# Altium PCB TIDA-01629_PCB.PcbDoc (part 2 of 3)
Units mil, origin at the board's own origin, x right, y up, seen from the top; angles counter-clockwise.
Board outline 2351.88 x 2559.06 mil, 4 copper layers (Top Layer, GND, POWER, Bottom Layer), stack 60.63 mil thick; 223 components, 122 nets, 655 pads, 542 vias.
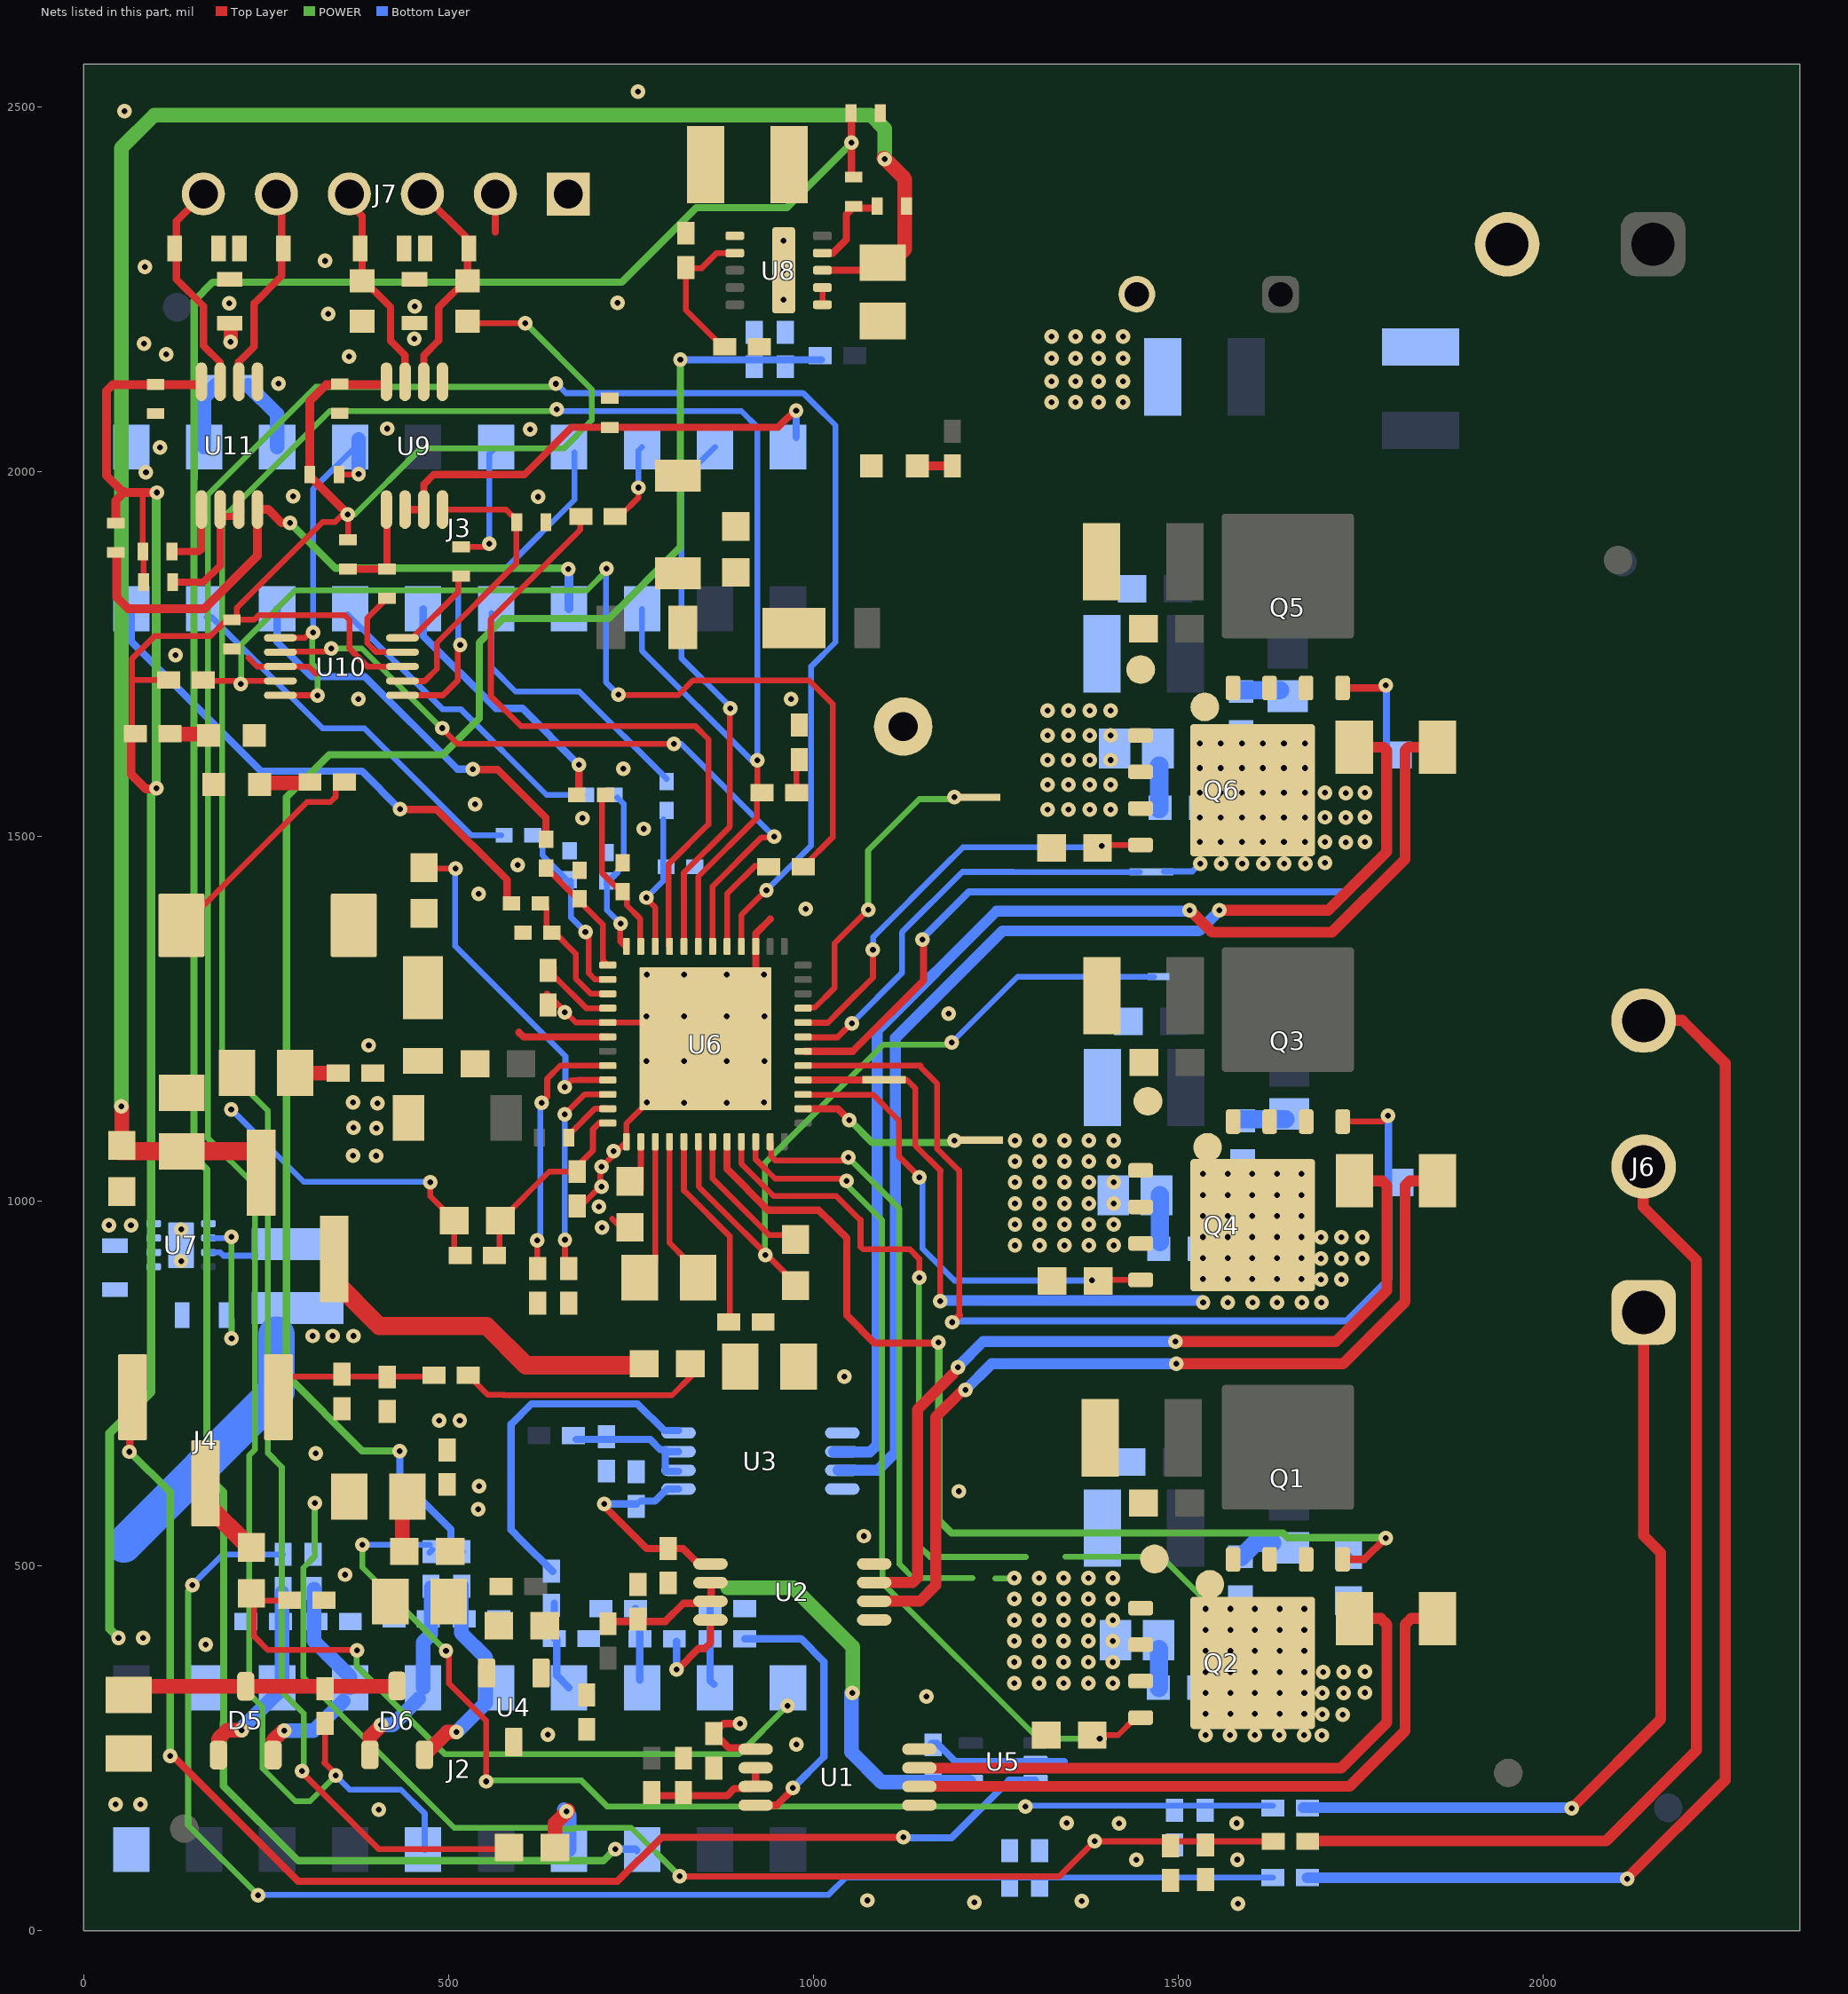
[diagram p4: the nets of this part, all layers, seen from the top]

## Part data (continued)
R5 R9 R14 R16: library part CMP-0026822-2, "RES, 0, 5%, 0.063 W, 0402", Manufacturer=Vishay-Dale, Power_W=63mW, Supplier Part Number 1=541-0.0JCT-ND, TempCo="200 ppm/C", Tolerance_%=5%, Value2=0.063W, Value_Code=0000, ValueDisplayed=0
R13: library part CMP-0022321-5, "RES, 301, 1%, 0.1 W, AEC-Q200 Grade 0, 0603", Manufacturer=Vishay-Dale, Power_W=100mW, Supplier Part Number 1=541-301HCT-ND, TempCo="100 ppm/C", Tolerance_%=1%, Value2=0.1W, Value_Code=301R, ValueDisplayed=301
R15: library part CMP-0022270-4, "RES, 2.10 k, 1%, 0.1 W, AEC-Q200 Grade 0, 0603", Manufacturer=Vishay-Dale, Power_W=100mW, Supplier Part Number 1=541-2.10KHCT-ND, TempCo="100 ppm/C", Tolerance_%=1%, Value2=0.1W, Value_Code=2k10, ValueDisplayed=2.10k
R18: library part CMP-0025958-3, "RES, 10.0 k, 1%, 0.063 W, AEC-Q200 Grade 0, 0402", Manufacturer=Vishay-Dale, Power_W=63mW, Supplier Part Number 1=541-10.0KLCT-ND, TempCo="100 ppm/C", Tolerance_%=1%, Value2=0.063W, Value_Code=10k0, ValueDisplayed=10.0k
R19: library part CMP-0026050-3, "RES, 17.4 k, 1%, 0.063 W, AEC-Q200 Grade 0, 0402", Manufacturer=Vishay-Dale, Power_W=63mW, Supplier Part Number 1=541-17.4KLCT-ND, TempCo="100 ppm/C", Tolerance_%=1%, Value2=0.063W, Value_Code=17k4, ValueDisplayed=17.4k
R20 R22 R23 R32 R33 R36: library part CMP-0020521-2, "RES, 2.7, 5%, 0.125 W, 0805", Manufacturer=Vishay-Dale, Power_W=125mW, Supplier Part Number 1=541-2.7ACT-ND, TempCo="200 ppm/C", Tolerance_%=5%, Value2=0.125W, Value_Code=2R70, ValueDisplayed=2.7
R24 R25 R26 R27 R28 R29: library part CMP-0026164-2, "RES, 20.0, 1%, 0.063 W, AEC-Q200 Grade 0, 0402", Manufacturer=Vishay-Dale, Power_W=63mW, Supplier Part Number 1=541-20.0LCT-ND, TempCo="100 ppm/C", Tolerance_%=1%, Value2=0.063W, Value_Code=20R0, ValueDisplayed=20.0
R30: library part CMP-0026852-2, "RES, 1.0 k, 5%, 0.063 W, 0402", Manufacturer=Vishay-Dale, Power_W=63mW, Supplier Part Number 1=541-1.0KJCT-ND, TempCo="200 ppm/C", Tolerance_%=5%, Value2=0.063W, Value_Code=1k00, ValueDisplayed=1.0k
R31 R46 R47 R48 R49 R51 R52 R53 R56 R57: library part CMP-0026880-3, "RES, 22, 5%, 0.063 W, AEC-Q200 Grade 0, 0402", Manufacturer=Vishay-Dale, Power_W=63mW, Supplier Part Number 1=541-22JCT-ND, TempCo="200 ppm/C", Tolerance_%=5%, Value2=0.063W, Value_Code=22R0, ValueDisplayed=22
R34: library part CMP-0026404-2, "RES, 49.9, 1%, 0.063 W, AEC-Q200 Grade 0, 0402", Manufacturer=Vishay-Dale, Power_W=63mW, Supplier Part Number 1=541-49.9LCT-ND, TempCo="100 ppm/C", Tolerance_%=1%, Value2=0.063W, Value_Code=49R9, ValueDisplayed=49.9
R35: library part CMP-0026825-4, "RES, 10 k, 5%, 0.063 W, 0402", Manufacturer=Vishay-Dale, Power_W=63mW, Supplier Part Number 1=541-10KJCT-ND, TempCo="200 ppm/C", Tolerance_%=5%, Value2=0.063W, Value_Code=10k0, ValueDisplayed=10k
R37 R45: library part CMP-0020442-2, "RES, 0, 5%, 0.125 W, 0805", Manufacturer=Vishay-Dale, Power_W=125mW, Supplier Part Number 1=541-0.0ACT-ND, TempCo="200 ppm/C", Tolerance_%=5%, Value2=0.125W, Value_Code=0000, ValueDisplayed=0
R38: library part CMP-0026162-2, "RES, 20.0 k, 1%, 0.063 W, AEC-Q200 Grade 0, 0402", Manufacturer=Vishay-Dale, Power_W=63mW, Supplier Part Number 1=541-20.0KLCT-ND, TempCo="100 ppm/C", Tolerance_%=1%, Value2=0.063W, Value_Code=20k0, ValueDisplayed=20.0k
R39: library part CMP-0026879-3, "RES, 22 k, 5%, 0.063 W, AEC-Q200 Grade 0, 0402", Manufacturer=Vishay-Dale, Power_W=63mW, Supplier Part Number 1=541-22KJCT-ND, TempCo="200 ppm/C", Tolerance_%=5%, Value2=0.063W, Value_Code=22k0, ValueDisplayed=22k
R40: library part CMP-0026646-1, "RES, 0.91, 1%, 0.125 W, 0402", Manufacturer=Panasonic, Power_W=125mW, Supplier Part Number 1=P.91AKCT-ND, TempCo="250 ppm/C", Tolerance_%=1%, Value2=0.125W, Value_Code=R910, ValueDisplayed=0.91
R41: library part CMP-0026280-2, "RES, 301 k, 1%, 0.063 W, AEC-Q200 Grade 0, 0402", Manufacturer=Vishay-Dale, Power_W=63mW, Supplier Part Number 1=541-301KLCT-ND, TempCo="100 ppm/C", Tolerance_%=1%, Value2=0.063W, Value_Code=301k
R42: library part CMP-0025956-2, "RES, 107 k, 1%, 0.063 W, 0402", Manufacturer=Vishay-Dale, Power_W=63mW, Supplier Part Number 1=541-107KLCT-ND, TempCo="100 ppm/C", Tolerance_%=1%, Value2=0.063W, Value_Code=107k
R43: library part CMP-0026405-2, "RES, 4.02 k, 1%, 0.063 W, AEC-Q200 Grade 0, 0402", Manufacturer=Vishay-Dale, Power_W=63mW, Supplier Part Number 1=541-4.02KLCT-ND, TempCo="100 ppm/C", Tolerance_%=1%, Value2=0.063W, Value_Code=4k02, ValueDisplayed=4.02k
R44: library part CMP-0026856-5, "RES, 1.5 k, 5%, 0.063 W, AEC-Q200 Grade 0, 0402", Manufacturer=Vishay-Dale, Power_W=63mW, Supplier Part Number 1=541-1.5KJCT-ND, TempCo="200 ppm/C", Tolerance_%=5%, Value2=0.063W, Value_Code=1k50, ValueDisplayed=1.5k
R50 R54: library part CMP-0025758-3, "RES, 22, 5%, 0.1 W, 0603", Manufacturer=Vishay-Dale, Power_W=100mW, Supplier Part Number 1=541-22GCT-ND, TempCo="200 ppm/C", Tolerance_%=5%, Value2=0.1W, Value_Code=22R0, ValueDisplayed=22
R55: library part CMP-0027004-2, "RES, 0, 5%, 0.063 W, 0402", Manufacturer="Yageo America", Power_W=63mW, Supplier Part Number 1=311-0.0JRCT-ND, TempCo="200 ppm/C", Tolerance_%=5%, Value2=0.063W, Value_Code=0000, ValueDisplayed=0
R58: library part CMP-0026840-2, "RES, 150 k, 5%, 0.063 W, AEC-Q200 Grade 0, 0402", Manufacturer=Vishay-Dale, Power_W=63mW, Supplier Part Number 1=541-150KJCT-ND, TempCo="200 ppm/C", Tolerance_%=5%, Value2=0.063W, Value_Code=150k
R60 R62: library part CMP-0026822-3, "RES, 0, 5%, 0.063 W, AEC-Q200 Grade 0, 0402", Manufacturer=Vishay-Dale, PartNumber=CRCW04020000Z0ED, Power_W=63mW, Supplier Part Number 1=541-0.0JCT-ND, TempCo="200 ppm/C", Tolerance_%=5%, Value2=0.063W, Value_Code=0000, ValueDisplayed=0
R61: library part CMP-0026195-2, "RES, 24.3 k, 1%, 0.063 W, AEC-Q200 Grade 0, 0402", Manufacturer=Vishay-Dale, Power_W=63mW, Supplier Part Number 1=541-24.3KLCT-ND, TempCo="100 ppm/C", Tolerance_%=1%, Value2=0.063W, Value_Code=24k3, ValueDisplayed=24.3k
R63 R65 R67 R70 R71 R73 R74 R75: library part CMP-0026938-4, "RES, 4.7 k, 5%, 0.063 W, 0402", Manufacturer=Vishay-Dale, Power_W=63mW, Supplier Part Number 1=541-4.7KJCT-ND, TempCo="200 ppm/C", Tolerance_%=5%, Value2=0.063W, Value_Code=4k70, ValueDisplayed=4.7k
R64 R72: library part CMP-0022109-5, "RES, 1.00 k, 1%, 0.1 W, AEC-Q200 Grade 0, 0603", Manufacturer=Vishay-Dale, Power_W=100mW, Supplier Part Number 1=541-1.00KHCT-ND, TempCo="100 ppm/C", Tolerance_%=1%, Value2=0.1W, Value_Code=1k00, ValueDisplayed=1.00k
R66: library part CMP-0026880-2, "RES, 22, 5%, 0.063 W, 0402", Manufacturer=Vishay-Dale, Power_W=63mW, Supplier Part Number 1=541-22JCT-ND, TempCo="200 ppm/C", Tolerance_%=5%, Value2=0.063W, Value_Code=22R0, ValueDisplayed=22
R68 R69 R76 R77: library part CMP-0023196-3, "RES, 59.0, 1%, 0.1 W, 0603", Manufacturer="Yageo America", PartNumber=RC0603FR-0759RL, Power_W=100mW, Supplier Part Number 1=311-59.0HRCT-ND, TempCo="200 ppm/C", Tolerance_%=1%, Value2=0.1W, Value_Code=59R0, ValueDisplayed=59.0
TP1: library part CMP-0055138-1, "Test Point, Miniature, Black, TH", Color=Black, Manufacturer=Keystone, Supplier Part Number 1=36-5001-ND
TP2 TP3 TP4 TP5 TP6 TP7: library part CMP-0003825-1, "1mm Test Point, SMT", Manufacturer=Any
U1 U2 U3: library part CMP-0075735-1, "High/Low Side, Bi-Directional Zero-Drift Current Sense Amp w/ Enhanced PWM Rejection, PW0008A (TSSOP-8)", Alternate Manufacturer="Texas Instruments", Alternate PartNumber=INA240A2PW
U4: library part CMP-0033032-1, "Automotive Catalog Low-Voltage Adjustable Precision Shunt Regulator, 15 mA, -40 to 125 degC, 3-pin SOT-23 (DBZ), Green (RoHS & no Sb/Br)", Manufacturer="Texas Instruments", Rating=Automotive
U5: library part CMP-0013250-2, "TMP235DCK, DCK0005A (SOT-5)", Alternate Manufacturer="Texas Instruments"
U6: library part CMP-0013783-2, "100-V Three-Phase Smart Gate Driver, RGZ0048L (VQFN-48)", Alternate Manufacturer="Texas Instruments", Alternate PartNumber=DRV8350RSRGZT
U7: library part CMP-0037789-2, "Buck Step Down Regulator with 3 to 17 V Input and 3.3 V Output, -40 to 85 degC, 8-Pin WSON (DSG), Green (RoHS & no Sb/Br)", Manufacturer="Texas Instruments", PartNumber=TPS62162DSGR, Rating=Catalog, Switch Current Limit(Typ)(A)=1.8
U8: library part CMP-0065261-5, "36-V 1-A Step-Down DC-DC Nano Module, SIL0010A (uSIP-10)", Alternate Manufacturer="Texas Instruments", Alternate PartNumber=LMZM23601SILT
U9 U11: library part CMP-0074780-2, "5-V RS-485 Transceivers With +/-16-kV IEC ESD Protection, DGK0008A (VSSOP-8)", Alternate Manufacturer="Texas Instruments", Alternate PartNumber=THVD1550DGK
U10: library part CMP-0067418-1, "DUAL 10-Ohm SPDT ANALOG SWITCH, DGS0010A (VSSOP-10)", Alternate Manufacturer="Texas Instruments", Alternate PartNumber=TS5A23157DGST
ZZ1: library part CMP-0003616-3
ZZ2 ZZ3 ZZ4: library part AssemblyNote

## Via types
v1: diameter 20, hole 8, Top Layer to Bottom Layer, tented both sides, 525 vias
v2: diameter 19.68, hole 7.87, Top Layer to Bottom Layer, 17 vias

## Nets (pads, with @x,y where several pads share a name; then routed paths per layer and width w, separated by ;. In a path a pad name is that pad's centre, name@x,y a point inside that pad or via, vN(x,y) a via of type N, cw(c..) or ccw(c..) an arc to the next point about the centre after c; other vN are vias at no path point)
3V3: C58.1 C69.1 C70.1 C72.1 D5.3 D6.3 L4.1 L5.2 R30.2 R35.2 R44.2 R45.1 R64.2 R65.2 R67.2 R73.2 R74.2 R75.2 U7.6 U9.8 U10.8 U11.8 | length 4884.4
  Top Layer w8: R44.2@66.36,1638.86 66.36,1743.53 97.91,1775.08 174.32,1775.08 195.1,1795.86 210.1,1795.86 210.1,1813.45 327.77,1931.12 344.88,1931.12 355.22,1941.46 v1(362.08,1941.46) 362.5,1941.46 R65.2@362.5,1906.81 ; 67.14,1714.81 R30.2@116.85,1714.81 ; R73.2@81.41,1890.81 81.41,1971.59 ; R75.2@82.21,1848.63 R73.2@82.21,1886.42 ; C70.1@203.34,1797.12 233.8,1797.12 239.94,1803.26 304.97,1803.26 305.08,1803.37 358.29,1803.37 364.4,1797.26 364.4,1758.84 364.91,1758.33 ; 364.23,1758.16 389.34,1733.06 U10.8@437.16,1733.06 ; R64.2@527.35,2203.62 v1(605.28,2203.62)
  Top Layer w12: R74.2@44.31,1929.59 44.31,1960.78 56.26,1972.73 ; 54.55,2119.28 40.15,2119.28 31.54,2110.66 31.54,1994.55 53.36,1972.73 56.26,1972.73 ; 54.55,2119.36 161.96,2119.36 U11.8@162.53,2119.93 ; 56.32,1972.79 56.26,1972.73 ; R44.2@65.34,1634.99 65.34,1585.57 85.47,1565.43 v1@99.57,1565.43 ; v1(100.57,1971.59) 81.41,1971.59 57.4,1971.59 56.26,1972.73 ; v1@362.63,1941.82 362.54,1941.92 310.36,1994.09 310.36,2097.06 332.67,2119.36 U9.8@415.07,2119.36
  Top Layer w20: R45.1@68.03,326.66 76.93,335.56 D6.3@418.4,335.56
  POWER w8: v1@203.08,815.86 203.08,838.23 v1(203.05,951.31) ; v1@362.54,1941.54 371.93,1941.54 462.28,2031.89 658.05,2031.89 696.49,2070.33 696.49,2112.53 ; v1@605.61,2203.9 696.74,2112.78
  POWER w12: v1@50.02,400.32 36.04,414.3 36.04,682.45 92.66,739.07 92.66,1559.22 v1(99.92,1566.48) v1@99.92,1972.3
  Bottom Layer w8: U7.6@171.25,949.74 v1@206.09,949.74
  Bottom Layer w50: 55.24,529.82 264.61,739.19 264.61,817.47
  other v1: 48.06,401.79 82.04,401.79 487.35,699.56 515.73,699.56 203.08,812.34 314.01,815.51 341.67,815.51 370.05,815.51
3V3_Analog: C1.1 C5.1 C8.1 C12.1 C56.1 L4.2 R13.1 U1.5 U2.5 U3.5 U5.4 | length 971.4
  Top Layer w10: v1@712.12,583.83 771.66,524.29 C5.1@801,524.29 ; C5.1@802.8,525.3 803.82,524.29 821.86,524.29 843.01,503.14 U2.5@859.19,503.14 ; v1(899.79,284.39) 877.5,284.39 C1.1@863.72,270.62 865.03,270.62 884.47,251.18 U1.5@925.57,251.18
  Top Layer w20: R13.1@436.7,519.49 C56.1@436.7,571.13
  POWER w20: 882.91,470.37 973.06,470.37 1054,389.43 v1@1054,326.88
  Bottom Layer w10: v1(713.58,585.41) C8.1@758.05,585.41 ; C8.1@764.23,589.41 783.08,589.41 799.53,605.87 U3.5@815.45,605.87
  Bottom Layer w20: v1@1052.26,326.3 1052.26,245.28 1093.69,203.86 U5.4@1213.39,203.86
  other v1: 1053.42,326.3 540.96,577.88 542,609.49
3V3_Launch: J2.1 R45.2
  other v1: 44.2,173.76 78.18,173.76
15V: C67.1 J1.1 L6.1 R37.2 R60.2 U8.3 | length 2896.3
  Top Layer w10: U8.3@1012.64,2276.19 C67.1@1084.73,2276.19
  Top Layer w20: L6.1@52.61,1076.67 v1@52.61,1129.8 ; v1@1097.01,2430.11 1125.62,2401.5 1125.62,2305.16 C67.1@1102.92,2282.45
  Top Layer w25: L6.1@49.3,1068.7 R37.2@134.58,1068.7 J1.1@224.43,1068.7
  POWER w20: v1(52.02,1130.38) 52.02,2444.05 96.87,2488.9 1079.17,2488.9 1097.77,2470.29 v1@1097.77,2428.98
  other v1: 1098.1,2428.53
CLK_N: J7.6 R77.2 U11.7 | length 352.1
  Top Layer w10: 127.35,2264.04 163.88,2227.51 ; 127.44,2263.94 127.44,2343.8 J7.6@164.41,2380.76 ; U11.7@187.02,2123.48 187.02,2150.38 164.93,2172.47 ; 164.93,2172.47 164.5,2172.9 164.5,2226.89 164.03,2227.36 164.93,2172.47
CLK_P: J7.5 R76.1 U11.6 | length 284.7
  Top Layer w10: U11.6@212.61,2123.48 212.61,2150.65 233.87,2171.91 233.87,2230.87 271.55,2268.55 271.55,2306.12 271.55,2373.62 J7.5@264.41,2380.76
DATA_N: J7.4 R69.2 R72.2 U9.7 | length 289.3
  Top Layer w10: J7.4@364.41,2380.76 364.41,2368.12 381.86,2350.67 381.86,2263.96 382.6,2263.96 420.66,2225.9 420.66,2179.56 440.72,2159.51 U9.7@440.72,2123.48
DATA_P: J7.3 R64.1 R68.1 U9.6 | length 285
  Top Layer w10: U9.6@466.31,2123.48 466.31,2159.51 486.68,2179.88 486.68,2225.03 525.73,2264.08 526.4,2264.08 R68.1@526.4,2306.12 ; J7.3@469.71,2376.21 R68.1@524.21,2321.72
EN_DRV: R57.2 U6.33 | length 926.1
  Top Layer w8: 579.44,1819.27 680.99,1920.81 R57.2@680.99,1937.42 ; 579.53,1819.18 558.26,1797.91 558.26,1692.61 599.25,1651.63 837.99,1651.63 856.54,1633.08 856.54,1517.27 ; U6.33@803.15,1349.48 802.03,1350.6 802.03,1462.76 856.54,1517.27 ; 856.54,1516.34 856.54,1517.27
ENC_CLK: J3.13 R74.1 U11.4 | length 868.3
  Top Layer w12: R74.1@45.45,1885.47 45.45,1828.05 61.41,1812.08 165.72,1812.08 238.51,1884.88 U11.4@238.51,1948.28 253.36,1948.28 271.78,1929.86 v1@282.18,1929.86
  POWER w10: v1(282.98,1930.05) 345.03,1868 v1@665.41,1868
  Bottom Layer w12: v1@664.96,1870.24 665.44,1869.76 J3.13@665.44,1812.21
  other v1: 664.42,1866.85
ENC_DIRCTRL: J3.20 R71.2 U9.2 U9.3 | length 652
  Top Layer w10: U9.2@440.72,1948.28 U9.3@465.85,1948.28 ; U9.3@469.18,1945.41 U9.3@466.31,1948.28 466.31,1982.51 480.01,1996.22 604.32,1996.22 669.01,2060.91 951.99,2060.91 v1@975.95,2084.87
  Bottom Layer w10: J3.20@976.65,2047.38 v1(976.65,2083.91)
ENC_PS_EN: J2.15 R62.2 R63.2 | length 3744.7
  Top Layer w10: R62.2@1052.47,2406.21 v1(1052.47,2451.19) R63.2@1052.47,2490.81
  POWER w10: v1@728.38,112.23 712.54,96.38 294.32,96.38 191.77,198.93 191.77,285.71 192.23,286.17 192.23,601.77 169.1,624.9 169.1,1043.62 151.5,1061.22 151.5,1990.24 151.76,1990.51 151.76,2234.34 177.24,2259.82 737.7,2259.82 839.77,2361.89 964.17,2361.89 v1@1053.46,2451.19
  Bottom Layer w10: v1(728.61,112.17) 756.4,112.17 J2.15@758.21,110.36
GND: C1.2 C2.2 C3.2 C4.2 C5.2 C6.2 C7.2 C8.2 C9.2 C10.2 C11.2 C12.2 C13.1 C14.2 C15.2 C16.2 C19.2 C20.2 C21.2 C22.2 C23.2 C24.2 C27.2 C29.2 C30.2 C31.2 C32.2 C34.2 C35.2 C36.2 C37.2 C38.2 C39.2 C41.2 C42.2 C43.2 C44.2 C45.2 C50.2 C51.2 C52.2 C53.2 C54.2 C55.2 C56.2 C57.2 C58.2 C59.2 C60.2 C61.2 C62.2 C63.2 C64.2 C65.2 C66.2 C67.2 C68.2 C69.2 C70.2 C71.2 C72.2 C73.2 C75.2 C77.2 C79.2 D1.2 D3.1 D4.1 D7.1 J2.4 J3.2 J5.2 J7.2 NT3.2 NT5.2 NT7.2 Q2.1 Q2.2 Q2.3 Q4.1 Q4.2 Q4.3 Q6.1 Q6.2 Q6.3 R4.1 R6.1 R10.1 R17.1 R18.1 R19.2 R22.1 R32.1 R36.1 R40.1 R42.1 R43.1 R61.1 R63.1 R70.1 R71.1 R72.1 TP1.1 TP5.1 TP6.1 TP7.1 U1.1 U1.4 U2.1 U2.4 U3.1 U3.4 U4.3 U5.2 U6.1 U6.27 U6.41 U6.49@852.36,1223.02 U7.1 U7.4 U7.5 U7.9@133.85,939.9 U8.1 U8.2 U8.11@959.49,2276.19 U9.5 U10.3 U11.5 | length 908.6
  Top Layer w7.87: 226.18,1745.01 238.14,1733.06 U10.3@269.83,1733.06 308.71,1733.06 318.34,1723.43 ; U8.1@1012.64,2228.95 U8.2@1012.64,2250.61
  Top Layer w8: C27.2@634.66,1284.4 635.56,1284.4 654.48,1265.48 674.82,1245.15 U6.41@718.5,1245.15 U6.49@790.47,1245.15 ; R43.1@680.38,992.82 708.34,1020.77 708.34,1045.65 v1@727.89,1065.19 ; 724.45,976.34 C54.2@735.06,965.73 ; v1@729.16,1066.46 v1@727.89,1065.19 ; U6.49@785.07,1147.64 744.16,1106.73 744.16,1081.83 U6.1@744.09,1081.76 727.89,1065.56 v1@727.89,1065.19
  Top Layer w10: 564.41,2328.62 J7.2@564.41,2380.76 ; U6.49@921.26,1293.16 U6.27@921.26,1349.48 921.26,1367.05 941.08,1386.88
  Top Layer w11.81: C73.2@200.26,2203.58 C73.2@201.76,2202.08
  Top Layer w19.68: v1(201.76,2177.98) C73.2@201.76,2202.08
  POWER w7.87: NT3.2@1249.47,483.07 1273.48,483.07 v1@1274.94,481.61
  Bottom Layer w9.84: C12.2@1162.1,257.48 1169.49,257.48 1194.9,232.07 U5.2@1304.56,232.07 1344,232.07
  other v1: 1582.14,37.47 1220.62,39.1 1367.83,40.9 1074.3,41.95 1442.63,97.58 1581.16,97.87 1418.92,147.34 1580.06,147.81 1347.41,148.15 404.88,166.38 976.77,255.88 636.56,269.3 1155.31,321.24 1275.6,339.75 1309.4,339.75 1343.2,339.75 1377,339.75 1410.79,339.75 1275.6,368.55 1309.4,368.55 1343.2,368.55 1377,368.55 1410.79,368.55 167.39,392.31 1275.6,397.36 1309.4,397.36 1343.2,397.36 1377,397.36 1410.79,397.36 1275.6,426.17 1309.4,426.17 1343.2,426.17 1377,426.17 1410.79,426.17 1275.6,454.97 1309.4,454.97 1343.2,454.97 1377,454.97 1410.79,454.97 1275.6,483.78 1309.4,483.78 1343.2,483.78 1377,483.78 1410.79,483.78 358.74,488.36 1069.36,541.23 1199.78,602.65 318.16,654.69 1042.49,759.75 1276.49,939.61 1310.28,939.61 1344.08,939.61 1377.88,939.61 1411.68,939.61 710.49,964.43 1276.49,968.42 1310.28,968.42 1344.08,968.42 1377.88,968.42 1411.68,968.42 706.11,992.63 1276.49,997.23 1310.28,997.23 1344.08,997.23 1377.88,997.23 1411.68,997.23 709.84,1020.34 1276.49,1026.03 1310.28,1026.03 1344.08,1026.03 1377.88,1026.03 1411.68,1026.03 709.84,1047.39 1276.49,1054.84 1310.28,1054.84 1344.08,1054.84 1377.88,1054.84 1411.68,1054.84 369.7,1062.83 400.97,1062.41 726.23,1068.88 1276.49,1083.64 1310.28,1083.64 1344.08,1083.64 1377.88,1083.64 1411.68,1083.64 370.12,1100.86 401.39,1100.44 402.66,1134.25 369.7,1135.94 772.08,1135.96 932.74,1135.96 390.99,1213.86 1185.38,1257.31 659.7,1259.07 772.08,1310.87 932.74,1310.87 989.75,1400.95 541.62,1421.43 595.22,1461.27 767.99,1510.65 683.99,1525.19 1321.21,1537.3 1350.01,1537.3 1378.82,1537.3 1407.62,1537.3 536.7,1544.54 1321.21,1571.09 1350.01,1571.09 1378.82,1571.09 1407.62,1571.09 739.97,1593.12 1321.21,1604.89 1350.01,1604.89 1378.82,1604.89 1407.62,1604.89 1321.21,1638.69 1350.01,1638.69 1378.82,1638.69 1407.62,1638.69 1321.21,1672.49 1350.01,1672.49 1378.82,1672.49 1407.62,1672.49 376.58,1688.48 969.57,1688.44 126.35,1748.61 622.89,1965.55 287.11,1966.61 85.71,1999.22 104.73,2033.08 611.98,2058.03 416.43,2059.15 1326.52,2095.16 1359.72,2095.16 1390.92,2095.16 1424.72,2095.16 267.36,2120.87 1326.52,2123.96 1359.72,2123.96 1390.92,2123.96 1424.72,2123.96 1326.52,2155.52 1359.72,2155.52 1390.92,2155.52 1424.72,2155.52 364.15,2158.18 113.61,2161 82.85,2175.46 453.45,2182.4 1326.52,2185.31 1359.72,2185.31 1390.92,2185.31 1424.72,2185.31 335.34,2216.43 453.72,2226.95 199.57,2230.91 732,2231.55 84.45,2280.88 331.27,2289.09 56.1,2494.09 760.05,2520.94
  other v2: 133.85,918.25 133.85,961.56 823.23,1134.91 881.5,1134.91 771.65,1192.12 823.23,1192.12 881.5,1192.12 933.07,1192.12 771.65,1253.93 823.23,1253.93 881.5,1253.93 933.07,1253.93 823.23,1311.13 881.5,1311.13 959.49,2235.64 959.49,2276.19 959.49,2316.74
I_A: R53.2 U1.8 | length 374.6
  Top Layer w10: U1.8@921.1,172.41 950.15,172.41 v1@972.27,194.53
  Bottom Layer w10: R53.2@906.11,400.5 983.13,400.5 1014.65,368.98 1014.65,290.91 1014.67,238.68 v1(971.92,195.93) v1@970.59,197.26
I_B: R52.2 U2.8 | length 130.4
  Top Layer w10: v1@814.2,358.35 843.02,387.17 851.54,387.17 859.19,394.82 U2.8@859.19,426.37
  Bottom Layer w10: v1(812.68,358.25) R52.2@812.68,396.96
I_C: R51.2 U3.8 | length 482.3
  Bottom Layer w10: R51.2@643.14,492.43 600.84,534.73 600.84,534.82 585.97,549.68 585.97,561.13 585.97,694.7 613.91,722.64 759.22,722.64 795.99,685.86 U3.8@815.52,685.86
MUX_CHANNEL: J3.8 R67.1 U10.1 U10.5 | length 538
  Top Layer w8: U10.5@269.83,1693.69 v1@320.99,1693.69 ; U10.1@269.83,1772.43 303.46,1772.43 311.48,1780.45 v1@316.53,1780.45 ; R67.1@350.2,1996.38 v1@377.58,1996.38
  POWER w8: v1@313.46,1775.78 313.46,1736.72 320.83,1729.36 v1@320.83,1693.41
  Bottom Layer w8: v1(314.96,1779.52) 314.96,1976.33 J3.8@371.29,2032.65
  Bottom Layer w19.68: v1(377.01,1997.08) J3.8@377.01,2044.68
  other v1: 320.54,1693.52
NetC3_1: C3.1 R5.1 U1.6 U1.7 | length 164.4
  Top Layer w10: R5.1@777.61,185.54 882.21,185.54 891.8,195.13 U1.7@914.48,195.13 ; U1.7@921.1,200.09 U1.6@921.1,223.6
NetC6_1: C6.1 R9.1 U2.6 U2.7 | length 182.2
  Top Layer w10: R9.1@712.12,424.24 797.51,424.24 822.36,449.09 856.37,449.09 860.08,452.8 U2.6@860.08,475.23
NetC9_1: C9.1 R16.1 U3.6 U3.7 | length 194.3
  Bottom Layer w10: R16.1@675.2,673.73 776.49,673.73 790.3,659.92 797.13,659.92 U3.7@797.13,657.05 ; U3.7@815.45,657.05 U3.7@797.13,657.05 ; U3.6@815.64,630.06 797.13,630.06 U3.7@797.13,657.05
NetC11_1: C11.1 R13.2 R14.2 R15.2 U4.2
NetC17_2: C17.2 NT1.1 U6.6 | length 999.1
  Top Layer w8: U6.6@842.52,1081.76 842.96,1081.32 842.96,1020.21 ; 844.36,1018.81 C17.2@966.33,896.85
  POWER w8: v1@933.94,927.59 933.94,1052.82 1095.9,1214.78 v1@1192.16,1214.78
  Bottom Layer w8: v1(1189.94,1217.87) 1279.86,1307.79 NT1.1@1467,1307.79
  other v1: 934.16,926.56
NetC18_1: C18.1 R20.1 | length 50.8
  Bottom Layer w25: C18.1@1586.34,512.29 1605.94,531.89 R20.1@1629.03,531.89
NetC23_1: C23.1 C24.1 L1.2 R21.1 U6.5 | length 607.2
  Top Layer w8: R21.1@527.46,761.47 554.25,734.68 576.15,734.68 ; 576.15,734.3 806.7,734.3 L1.2@832.6,760.2 ; U6.5@822.83,1081.76 822.83,1014.83 826.73,1010.93 ; 825.12,1012.82 885.55,952.39 C24.1@885.55,830.09
NetC25_1: C25.1 U6.4 | length 172
  Top Layer w8: U6.4@803.15,1081.76 803.15,1049.03 803.06,1048.94 803.06,943.16 C25.1@826.63,919.59
NetC25_2: C25.2 U6.3 | length 181.2
  Top Layer w8: C25.2@764.3,895.14 C25.2@764.3,895.96 ; C25.2@771.93,906.38 783.02,917.47 783.35,917.47 783.35,1043.36 783.46,1043.48 U6.3@783.46,1081.76
NetC26_2: C26.2 R22.2 | length 52.9
  Bottom Layer w25: C26.2@1474.06,333.29 R22.2@1474.06,386.22
NetC27_1: C27.1 U6.40 | length 103.8
  Top Layer w8: C27.1@644.84,1320.71 644.84,1308.83 688.84,1264.83 U6.40@718.5,1264.83
NetC28_1: C28.1 R23.1 | length 62.9
  Bottom Layer w25: C28.1@1584.08,1112.4 R23.1@1647.01,1112.4
NetC33_2: C33.2 R32.2 | length 64.5
  Bottom Layer w25: C33.2@1474.88,943.92 R32.2@1474.88,1008.42
NetC40_1: C40.1 R33.1 | length 56.9
  Bottom Layer w25: C40.1@1582.93,1700.72 R33.1@1639.85,1700.72
NetC45_1: C45.1 R34.1 | length 43.7
  Top Layer w8: R34.1@977.22,1560.13 977.22,1599.62 C45.1@980.18,1602.58
NetC46_2: C46.2 R36.2 | length 59.3
  Bottom Layer w25: C46.2@1474.12,1537.92 R36.2@1474.12,1597.17
NetC47_1: C47.1 D1.1 L2.1 U6.42 | length 124.4
  Top Layer w10: 596.76,1231.74 603.03,1225.46 U6.42@718.5,1225.46
NetC47_2: C47.2 U6.45 | length 471.9
  Top Layer w8: C47.2@463.7,1456.35 v1(509.84,1456.35) ; v1(659.44,1156.67) 669.12,1166.35 678.07,1166.35 678.12,1166.41 U6.45@718.5,1166.41
  Bottom Layer w8: v1@509.45,1456.68 509.45,1349.87 660.4,1198.92 v1@660.4,1156.59
NetC48_1: C48.1 C49.1 L2.2 R37.1 R38.2 R39.2 | length 740.7
  Top Layer w8: L2.2@135.88,1376.96 306.39,1547.47 338.55,1547.47 345.97,1554.89 345.97,1575.42 R39.2@360.46,1575.42 ; v1@475.42,1027.02 475.42,1006.67 C48.1@508.32,973.77 R38.2@508.32,932.64
  Bottom Layer w8: v1(202.51,1126.1) 301.87,1026.73 v1@475.26,1026.73
  other v1: 475.32,1026.42
NetC48_2: C48.2 R38.1 R43.2 U6.48 | length 261.5
  Top Layer w8: R38.1@570.34,929.19 C48.2@570.34,974.8 ; C48.2@571.32,973.77 638.26,1040.71 657,1040.71 ; 657,1040.8 R43.2@680.38,1040.8 ; R43.2@680.38,1040.06 R43.2@680.38,1040.8 ; U6.48@707.24,1108.04 698.18,1098.98 698.18,1069.86 680.38,1052.07 R43.2@680.38,1040.8
NetC49_2: C49.2 R40.2 | length 57.3
  Top Layer w20: C49.2@290.31,1176.07 R40.2@347.61,1176.07
NetC52_1: C52.1 C53.1 D2.1 L3.1
NetC54_1: C54.1 U6.2 | length 65.7
  Top Layer w8: C54.1@763.78,1016.03 U6.2@763.78,1081.76
NetC55_1: C55.1 U6.44 | length 365.8
  Top Layer w8: C55.1@617.09,900.94 622.03,905.88 v1(622.03,946.76) ; v1(627.77,1135.18) 635.5,1142.91 635.5,1168.15 653.44,1186.09 U6.44@718.5,1186.09
  Bottom Layer w8: v1@626.21,944.54 626.21,1133.62 v1(627.77,1135.18)
NetC57_1: C57.1 L6.2 U7.2 U7.3
  other v1: 35.11,967.51 65.11,967.48
NetC59_1: C59.1 J2.18 R53.1 | length 105.7
  Bottom Layer w10: C59.1@858.84,441.81 858.84,343.21 J2.18@863.86,338.19
NetC60_1: C60.1 J2.16 R52.1 | length 100.5
  Bottom Layer w10: C60.1@756.34,441.81 762.37,435.79 J2.16@762.37,343.77
NetC61_1: C61.1 J2.14 R51.1 | length 122.7
  Bottom Layer w10: C61.1@645.15,400.81 R51.1@645.15,449.45 ; C61.1@648.61,400.4 648.61,350.1 J2.14@665.44,333.27
NetC62_1: C62.1 J2.20 R54.2 | length 937.7
  Top Layer w8: R54.2@231.59,463.41 242.12,452.89 C62.1@284.21,452.89 ; 233.86,416.53 R54.2@233.86,449.57 ; 234.01,416.53 234.01,403.68 252.52,385.17 v1@372.43,385.17
  POWER w8: v1@374.08,383.74 374.08,363.49 495.48,242.1 898.09,242.1 v1(964.69,308.7)
  other v1: 375,384.85
NetC63_1: C63.1 D6.2 J2.12 R49.1 | length 284.4
  Top Layer w20: D6.2@467.3,241.45 498.62,272.77 v1@507.4,272.77
  Bottom Layer w20: v1(511.15,272.55) 551.61,313 551.61,374.49 517.62,408.48 R49.1@517.62,473.06
NetC64_1: C64.1 D6.1 J2.10 R48.1 | length 254.4
  Top Layer w20: D6.1@392.5,241.45 392.5,266.4 v1@407.47,281.37
  Bottom Layer w20: v1(407.87,282.59) 423.74,282.59 J2.10@459.57,318.41 ; J2.10@465.44,333.27 465.44,395.81 476.2,406.57 R48.1@476.2,470.58
NetC65_1: C65.1 D5.2 J2.8 R47.1 | length 292.3
  Top Layer w20: D5.2@259.79,241.06 259.79,260.88 v1@272.63,273.72
  Bottom Layer w20: v1(274.95,274.46) 315.39,274.46 J2.8@356.11,315.18 ; R47.1@315.88,468.88 315.88,397.45 334.21,379.11 ; 334.44,379.33 365.44,348.33 J2.8@365.44,333.27
NetC66_1: C66.1 D5.1 J2.6 R46.1 | length 272.6
  Top Layer w20: D5.1@184.99,241.06 184.99,263.27 196.84,275.12 v1@217.08,275.12
  Bottom Layer w20: v1(216.61,275.42) 216.61,276.99 J2.6@265.22,325.6 ; J2.6@265.44,333.27 272.39,340.21 272.39,392.7 ; 272.29,382.82 R46.1@272.29,463.58
NetC71_1: C71.1 R68.2 R69.1
NetC73_1: C73.1 R76.2 R77.1
NetC74_1: C74.1 Q1.4 U6.8 | length 1499.3
  Top Layer w10: U6.8@881.89,1081.76 881.89,1044.6 938.62,987.87 1007.74,987.87 1023.22,972.39 ; 1020.9,974.82 1046.02,949.7 1046.02,843.83 1083.91,805.94 v1@1172.94,805.94 ; Q1.4@1721.02,509.4 Q1.4@1721.02,514.89 ; Q1.4@1725.49,509.4 1755.37,509.4 v1(1784.69,538.72)
  POWER w10: v1@1172.24,807.34 1172.24,562.75 1189.54,545.45 1643.95,545.45 1650.4,539 v1@1781.61,539
  Bottom Layer w8: C74.1@1733.44,515.95 1740.17,509.22 1755.19,509.22 v1(1784.69,538.72)
  other v1: 1171.36,806.54
NetC75_1: C75.1 Q2.4 U6.10 | length 1208.5
  Top Layer w8: U6.10@921.26,1081.76 921.26,1057.58 947.7,1031.14 v1@1042.89,1031.14 ; C75.1@1382.24,268.5 1417.81,268.5 Q2.4@1441.36,292.05 ; Q2.4@1448.96,292.05 Q2.4@1441.36,292.05 ; Q2.4@1458.27,292.48 Q2.4@1448.68,292.48 1441.79,292.48 Q2.4@1441.36,292.05
  POWER w8: v1@1045.31,1028.89 1045.31,1023.14 1094.6,973.85 1094.6,499.12 ; 1094.79,499.12 1094.79,477.19 1307.16,264.82 1307.4,264.82 1308.49,263.74 v1@1392.45,263.74
  other v1: 1392.66,263.7 1045.91,1027.91
NetC76_1: C76.1 Q3.4 U6.17 | length 1455.8
  Top Layer w8: U6.17@980.01,1186.09 1147.28,1186.09 ; 1145.71,1185.49 1169.77,1161.43 1169.77,1093.95 1169.74,1072.07 1199.43,1042.38 1200.42,1042.38 1200.42,844.18 ; Q3.4@1725.49,1109.37 1779.7,1109.37 v1@1787.2,1116.88
  Top Layer w10: v1(1190.58,834.34) 1200.42,844.18
  Bottom Layer w10: v1@1189.68,836.27 1731.16,836.27 1788.31,893.42 v1@1788.31,1116.34
  other v1: 1787.76,1117.43
NetC77_1: C77.1 Q4.4 U6.15 | length 650
  Top Layer w8: U6.15@989.3,1145.94 1082.42,1145.94 1117.55,1110.8 1117.55,1075.51 ; 1117.58,1075.17 1117.58,1061.1 v1(1145.56,1033.13) ; C77.1@1380.69,892.41 Q4.4@1448.68,892.41
  Bottom Layer w8: v1@1144.29,1031.84 1149.9,1026.22 1149.9,935.1 1193.49,891.51 v1@1383.1,891.51
  other v1: 1382.18,891.61
NetC78_1: C78.1 Q5.4 U6.18 | length 1229.8
  Top Layer w10: U6.18@989.13,1205.66 1054.08,1205.66 1151.23,1302.8 v1@1151.23,1357.79 ; Q5.4@1725.36,1703.67 1781.29,1703.67 v1@1785.24,1707.61
  Bottom Layer w10: v1@1148.86,1359.65 1213.48,1424.27 1536.56,1424.27 1536.71,1424.12 1728.35,1424.12 1785.53,1481.31 v1@1785.53,1705.07
  other v1: 1149.82,1358.95 1784.69,1707.42
NetC79_1: C79.1 Q6.4 U6.20 | length 596.9
  Top Layer w8: U6.20@988.81,1244.83 1020.06,1244.83 1028.91,1253.69 1028.91,1253.91 1042.87,1267.88 1043.1,1267.88 1081.84,1306.62 v1(1081.84,1344.75) ; C79.1@1396.56,1488.58 Q6.4@1448.55,1488.58
  Bottom Layer w8: v1@1082.15,1344.23 1082.15,1362.39 1181.72,1461.96 ; 1177.4,1457.67 1204.93,1485.2 v1@1395.06,1485.2
  other v1: 1395.47,1487.17
NetD3_2: D3.2 R39.1 | length 58.1
  Top Layer w20: D3.2@247.04,1573.58 R39.1@305.09,1573.58
NetD4_2: D4.2 R44.1 | length 60.4
  Top Layer w20: R44.1@115.27,1640.4 D4.2@175.66,1640.4
NetD7_2: D7.2 R58.1 | length 42.4
  Top Layer w12: D7.2@1142.77,2007.97 R58.1@1185.18,2007.97
NetJ1_2: J1.2 L1.1 | length 500.2
  Top Layer w25: J1.2@343.9,918.78 343.9,890.9 405.44,829.36 552.38,829.36 606.38,775.36 L1.1@768.39,775.36
NetJ2_13: J2.13 R50.2 | length 117.6
  Top Layer w20: R50.2@646.27,111.99 646.27,147.27 v1@663.95,164.94
  Bottom Layer w20: v1@658.6,166.13 665.44,159.29 J2.13@665.44,111.62
  other v1: 661.87,163.76
NetJ3_4: J3.4 R55.2 | length 91.8
  Bottom Layer w20: J3.4@165.44,2033.86 165.44,2102.5 R55.2@181.83,2118.89
NetJ3_6: J3.6 R55.1 | length 100.8
  Bottom Layer w20: R55.1@226,2118.32 265.44,2078.88 J3.6@265.44,2033.86
NetJ3_12: J3.12 R56.1 | length 173.1
  Top Layer w8: R56.1@517.55,1896.92 v1@557.76,1896.92
  Bottom Layer w8: v1@553.64,1900.88 556.24,1903.48 556.24,2024.66 J3.12@561.92,2030.33
  other v1: 556.24,1901.46
NetJ3_16: J3.16 R57.1 | length 106.5
  Top Layer w8: R57.1@735.66,1939.68 760.7,1964.73 v1(760.7,1978.31)
  Bottom Layer w8: v1(760.7,1978.31) 760.7,2029.12 J3.16@765.44,2033.86
NetJ4_2: J4.2 R54.1 | length 104.7
  Top Layer w25: J4.2@166.98,603.83 166.98,586.71 R54.1@228.88,524.81
NetL5_1: L5.1 U7.7 | length 65.8
  Bottom Layer w8: U7.7@171.25,930.06 187.46,930.06 191.92,925.59 L5.1@235.18,925.59
NetNT2_1: NT2.1 U6.9 | length 904.3
  Top Layer w8: U6.9@901.58,1081.76 901.58,1051.57 945.92,1007.22 1031.7,1007.22 1041.26,997.66 ; 1041.18,997.53 1063.9,974.81 1064.87,974.81 1064.87,937.78 1068.32,934.33 1132.31,934.33 1145.26,921.38 v1(1145.26,895.5) v1@1143.46,895.5
  POWER w8: 1144.91,740.1 v1@1144.91,894.95 ; 1144.9,747.22 1144.9,528.08 1160.28,512.7 NT2.1@1291.6,512.7
NetNT4_1: NT4.1 U6.16 | length 101.3
  Top Layer w10: U6.16@986.22,1166.41 NT4.1@1087.51,1166.41
NetNT6_1: NT6.1 U6.19 | length 590.5
  Top Layer w8: U6.19@994.45,1224.75 1033.2,1224.75 v1@1053.83,1245.38
  Bottom Layer w8: v1(1052.75,1244.03) 1121.55,1312.83 1121.55,1368.76 1204.38,1451.59 1273.81,1451.59 ; 1264.73,1451.52 NT6.1@1447.54,1451.52
NetR15_1: R15.1 R18.2 U4.1
NetR31_2: R31.2 U6.29 | length 139
  Top Layer w8: U6.29@881.89,1349.48 881.89,1421.52 920.08,1459.7 R31.2@933.07,1459.7
NetR41_1: R41.1 U6.47 | length 70.3
  Top Layer w8: R41.1@668.59,1087.41 668.59,1094.62 701.33,1127.36 U6.47@710.09,1127.36 ; U6.47@710.09,1127.45 U6.47@718.09,1127.45
NetR42_2: R42.2 U6.46 | length 289.5
  Top Layer w8: v1(659.33,1119.34) 686.72,1146.72 U6.46@718.5,1146.72 ; v1(659.85,947.44) 659.85,905.21 R42.2@663.59,901.46
  Bottom Layer w8: v1@659.69,946.59 v1@659.69,1118
NetR59_2: R59.2 R61.2 U8.7 | length 200.3
  Top Layer w8: R59.2@825.53,2279.76 825.53,2221.54 R61.2@875.48,2171.58 ; R59.2@829.67,2279.25 847.27,2279.25 867.83,2299.81 U8.7@892.56,2299.81
NetR60_1: R60.1 R62.1 U8.4 | length 120.3
  Top Layer w10: U8.4@1012.64,2299.81 1026.98,2299.81 1045.37,2318.2 1045.37,2352.94 R62.1@1055.21,2362.78 ; R62.1@1057.28,2361.3 R60.1@1088.6,2361.3
NetR65_1: R65.1 R66.2 U9.1 | length 132.7
  Top Layer w10: R65.1@362.5,1866.81 R66.2@416.07,1866.81 ; R66.2@416.07,1866.5 R66.2@416.07,1866.81 ; U9.1@416.07,1945.63 R66.2@416.07,1866.81
NetR66_1: R66.1 U10.9 | length 124.4
  Top Layer w8: R66.1@416.07,1826.5 388.91,1799.34 388.91,1765.13 401.27,1752.76 U10.9@435.58,1752.76
NetR70_2: R70.2 U9.4 U10.7 | length 401.2
  Top Layer w8: U10.7@446.79,1713.18 467.59,1713.18 484.34,1729.92 484.34,1765.73 593.49,1874.89 593.49,1933.8 579.02,1948.28 U9.4@491.9,1948.28
NetR73_1: R73.1 U11.1 | length 96.5
  Top Layer w10: R73.1@121.41,1890.81 158.07,1890.81 161.68,1894.42 ; 161.74,1893.51 U11.1@161.74,1948.28
NetR75_1: R75.1 U11.2 U11.3 | length 165.9
  Top Layer w10: R75.1@122.21,1848.63 164.42,1848.63 187.73,1871.93 187.73,1938.68 U11.3@207.65,1938.68 ; U11.3@212.92,1948.28 U11.3@215.8,1945.41
nFault: J2.9 R35.1 U6.28 | length 3924.5
  Top Layer w8: 330.25,230.74 v1@349.03,211.97 ; 330.88,229.29 R35.1@330.88,284.77 ; U6.28@901.58,1349.48 901.58,1392.59 v1@936.59,1427.6
  POWER w8: v1(345.69,212.98) 310.48,177.77 290.49,177.77 245.29,222.98 245.29,306.87 226.92,325.23 226.92,651.66 235.01,659.74 235.01,1021.96 170.34,1086.62 170.34,1968.23 318.47,2116.36 385.86,2116.36 ; 370.89,2116.32 642.94,2116.32 v1(647.24,2120.63)
  Bottom Layer w8: v1@345.26,213.42 v1(345.69,212.98) 364.91,193.77 435.01,193.77 467.64,161.14 J2.9@467.64,111.08 ; v1@647.07,2122.18 661.46,2107.8 984.37,2107.8 984.42,2107.75 986.53,2107.75 1000.49,2093.78 1000.49,2093.68 1030.4,2063.77 1030.4,1766.36 997.23,1733.2 997.23,1487.81 v1(935.93,1426.5)
PH_A_N: C18.2 C26.1 C74.2 NT2.2 Q1.1 Q1.2 Q1.3 Q2.5 Q2.6 Q2.7 Q2.8 Q2.9@1602.22,367.48 R2.1 TP2.1 U1.3 | length 1069.2
  Top Layer w15: U1.3@1153.25,223.28 1723.4,223.28 1786.08,285.97 1786.08,420.12 1777.86,428.33 R2.1@1741.49,428.33
  POWER w8: NT2.2@1345.39,512.9 1477.12,512.9 1537.81,452.21 v1(1537.81,441.48)
  other v1: 1537.49,268.42 1571.29,268.42 1605.09,268.42 1638.89,268.42 1672.68,268.42 1697.1,268.16 1725.62,296.39 1537.81,297.45 1571.61,297.45 1605.41,297.45 1639.21,297.45 1673,297.45 1697.41,297.19 1537.81,326.26 1571.61,326.26 1605.41,326.26 1639.21,326.26 1673,326.26 1697.41,326.26 1726.9,326.26 1756.07,326.57 1537.81,355.06 1571.61,355.06 1605.41,355.06 1639.21,355.06 1673,355.06 1698.7,355.06 1726.9,355.06 1756.07,355.37 1537.81,383.87 1571.61,383.87 1605.41,383.87 1639.21,383.87 1673,383.87 1537.81,412.67 1571.61,412.67 1605.41,412.67 1639.21,412.67 1673,412.67 1571.61,441.48 1605.41,441.48 1639.21,441.48 1673,441.48
PH_A_P: J6.1 R2.2 R3.1 U1.2 | length 1990.5
  Top Layer w15: U1.2@1153.25,198.28 1735.12,198.28 1749.76,212.93 1749.76,213.07 1811.08,274.39 1811.08,420.12 1819.29,428.33 R2.2@1855.67,428.33 ; v1@2039.98,168.78 2161.41,290.21 2161.41,518.4 2137.89,541.92 J6.1@2137.89,847.77
  Bottom Layer w15: R3.1@1671.27,168.97 v1@2039.59,168.97
  other v1: 2039.16,168.25
PH_B_N: C28.2 C33.1 C76.2 NT4.2 Q3.1 Q3.2 Q3.3 Q4.5 Q4.6 Q4.7 Q4.8 Q4.9@1602.22,967.41 R7.1 TP3.1 U2.3 | length 1880.6
  Top Layer w8: NT4.2@1112.09,1166.68 1128.32,1166.68 1140.03,1154.97 1140.03,1076.55 1174.8,1041.78 ; v1@1171.06,860.8 1174.26,864.01 1174.26,1041.79
  Top Layer w15: U2.3@1083.6,477.55 1136.26,477.55 1142.81,484.1 1142.81,714.63 1191.5,763.32 ; v1(1496.58,807.93) 1716.14,807.93 1786.08,877.87 1786.08,1021.73 1779.66,1028.15 R7.1@1741.49,1028.15
  Bottom Layer w15: v1@1177.37,864.23 v1@1532,864.23 ; v1@1198.43,773.63 1232.74,807.93 v1(1496.58,807.93)
  other v1: 1198.2,772.89 1534.35,861.18 1568.14,861.18 1601.94,861.18 1635.74,861.18 1669.54,861.18 1696.16,861.18 1173.86,863.14 1695.92,893.07 1723.93,893.07 1534.11,893.55 1567.91,893.55 1601.7,893.55 1635.5,893.55 1669.3,893.55 1695.92,921.88 1723.93,921.88 1752.51,921.88 1534.11,922.35 1567.91,922.35 1601.7,922.35 1635.5,922.35 1669.3,922.35 1695.92,950.69 1723.93,950.69 1752.51,950.69 1534.11,951.16 1567.91,951.16 1601.7,951.16 1635.5,951.16 1669.3,951.16 1534.11,979.96 1567.91,979.96 1601.7,979.96 1635.5,979.96 1669.3,979.96 1534.11,1008.77 1567.91,1008.77 1601.7,1008.77 1635.5,1008.77 1669.3,1008.77 1534.11,1037.57 1567.91,1037.57 1601.7,1037.57 1635.5,1037.57 1669.3,1037.57
PH_B_P: J6.2 R7.2 R8.1 U2.2 | length 2637.5
  Top Layer w15: U2.2@1083.6,451.96 1146.03,451.96 1167.81,473.75 1167.81,704.28 v1@1206.96,743.43 ; v1(1497.55,777.41) 1725.96,777.41 1811.08,862.52 1811.08,1021.73 1817.5,1028.15 R7.2@1855.67,1028.15 ; R8.1@1684.43,123.42 2086.37,123.42 2210.36,247.41 2210.36,919.41 2137.34,992.43 J6.2@2137.34,1036.96
  POWER w15: v1@1206.99,743.4 v1(1208.7,741.69)
  Bottom Layer w15: v1(1208.7,741.69) 1244.42,777.41 v1(1497.55,777.41)
PH_C_N: C40.2 C46.1 C78.2 NT6.2 Q5.1 Q5.2 Q5.3 Q6.5 Q6.6 Q6.7 Q6.8 Q6.9@1602.1,1563.58 R11.1 TP4.1 U3.3 | length 1708.7
  Top Layer w15: v1(1556.58,1399.06) 1705.66,1399.06 1785.95,1479.35 1785.95,1618.07 1781.44,1622.58 R11.1@1741.36,1622.58
  Bottom Layer w8: NT6.2@1480.41,1452.23 1519.53,1452.23 v1(1530.26,1462.96)
  Bottom Layer w15: U3.3@1034.12,631.67 1066.97,631.67 1067.23,631.41 1087.94,631.41 1095.27,638.74 1112.79,656.26 1112.79,1224.06 1259.4,1370.66 1528.73,1370.66 v1@1558.17,1400.1 ; U3.3@1039.86,631.46 1070.98,631.46 1071.2,631.67
  other v1: 1559.07,1462.96 1587.87,1462.96 1616.68,1462.96 1645.48,1462.96 1674.29,1462.96 1701.15,1464.04 1529.81,1492.54 1558.61,1492.54 1587.42,1492.54 1616.22,1492.54 1645.03,1492.54 1673.83,1492.54 1701.15,1492.47 1729.82,1492.13 1755.95,1492.68 1729.82,1525.93 1529.81,1526.34 1558.61,1526.34 1587.42,1526.34 1616.22,1526.34 1645.03,1526.34 1673.83,1526.34 1701.15,1526.45 1755.95,1526.48 1701.15,1560.06 1729.82,1559.73 1529.81,1560.13 1558.61,1560.13 1587.42,1560.13 1616.22,1560.13 1645.03,1560.13 1673.83,1560.13 1755.95,1560.28 1529.81,1593.93 1558.61,1593.93 1587.42,1593.93 1616.22,1593.93 1645.03,1593.93 1673.83,1593.93 1529.81,1627.73 1558.61,1627.73 1587.42,1627.73 1616.22,1627.73 1645.03,1627.73 1673.83,1627.73
PH_C_P: J6.3 R11.2 R12.1 U3.2 | length 3430.7
  Top Layer w15: v1@1515.05,1400.48 1546.66,1368.87 1710.82,1368.87 1810.95,1469 1810.95,1618.07 1815.47,1622.58 R11.2@1855.54,1622.58 ; v1@2116.04,73.22 2249.91,207.1 2249.91,1189.14 2190.84,1248.21 J6.3@2127.28,1248.21
  Bottom Layer w15: U3.2@1027.66,656.67 1077.33,656.67 1077.59,656.41 1087.79,666.62 1087.79,1234.41 1251.21,1397.83 v1@1516.28,1397.83 ; R12.1@1676.75,73.05 v1@2114.52,73.05
  other v1: 2115.28,71.7 1515.76,1399.06
PWM_AH: J3.11 R24.1 | length 377.9
  Bottom Layer w8: J3.11@559.18,1806.54 559.18,1731.82 592.07,1698.93 679.35,1698.93 R24.1@799.1,1579.17
PWM_AL: J3.9 R25.1 | length 367.6
  Top Layer w10: R25.1@672.25,1557.14 678.88,1563.77 v1(678.88,1598.29)
  Bottom Layer w10: J3.9@465.44,1812.21 465.44,1775.3 564.98,1675.76 601.41,1675.76 v1(678.88,1598.29)
PWM_BH: J3.7 R26.1 | length 424.7
  Bottom Layer w8: J3.7@361.95,1804.74 492.01,1674.68 516.98,1674.68 634.52,1557.14 R26.1@684.06,1557.14
PWM_BL: J3.5 R27.1 | length 546
  Top Layer w10: v1@533.31,1591.68 568.1,1591.68 633.75,1526.03 R27.1@633.75,1493.73
  Bottom Layer w10: J3.5@265.44,1812.21 265.44,1766.71 312.79,1719.36 385.51,1719.36 512.46,1592.41 v1(533.81,1592.41)
PWM_CH: J3.3 R28.1 | length 527.9
  Bottom Layer w8: J3.3@168.67,1801.15 174.98,1801.15 327.72,1648.41 385.12,1648.41 531.63,1501.9 R28.1@572.58,1501.9
PWM_CL: J3.1 R29.1 | length 724.2
  Top Layer w10: v1@436,1537.02 484.3,1537.02 580.52,1440.8 R29.1@580.52,1409.33
  Bottom Layer w10: J3.1@65.44,1812.21 65.44,1767.47 243.38,1589.53 381.78,1589.53 v1(433.83,1537.48)
PWM_DRV_AH: C39.1 R24.2 U6.34 | length 185.9
  Top Layer w8: v1@771.88,1418.36 771.88,1414.66 783.63,1402.91 U6.34@783.63,1350.56
  Bottom Layer w8: v1(771.35,1416.35) 794.87,1439.87 C39.1@794.87,1454.65 ; C39.1@794.55,1458.58 794.55,1523.72
PWM_DRV_AL: C36.1 R25.2 U6.35 | length 224.6
  Top Layer w8: R25.2@710.4,1551.93 710.4,1450.48 744.61,1416.27 744.61,1405.7 762.66,1387.64 762.66,1350.6 U6.35@763.78,1349.48
PWM_DRV_BH: C38.1 R26.2 U6.36 | length 257.2
  Top Layer w8: v1@735.59,1381.17 735.59,1355.89 U6.36@743.02,1348.45 ; U6.36@744.09,1349.48 U6.36@744.09,1355.5
  Bottom Layer w8: C38.1@716.64,1434.99 C38.1@717.22,1435.57 ; C38.1@716.64,1438.93 718.5,1438.93 731.92,1452.36 ; R26.2@731.56,1553.48 740.32,1544.72 740.32,1460.75 731.92,1452.36 ; v1(735.92,1380.67) 717.22,1399.37 C38.1@717.22,1435.57 ; C38.1@717.22,1435.57 731.92,1450.28 731.92,1452.36
PWM_DRV_BL: C35.1 R27.2 U6.37 | length 162.1
  Top Layer w8: R27.2@638.44,1452.87 711.68,1379.63 711.68,1330.71 U6.37@718.5,1323.89
PWM_DRV_CH: C37.1 R28.2 U6.38 | length 247.4
  Top Layer w8: v1@687.51,1367.95 692.58,1362.88 692.58,1312.56 700.94,1304.2 U6.38@718.5,1304.2
  Bottom Layer w8: 629,1503.38 629,1474.24 C37.1@666.21,1437.02 ; C37.1@667.82,1439.94 667.82,1389.45 v1(687.84,1369.44)
PWM_DRV_CL: C34.1 R29.2 U6.39 | length 187.3
  Top Layer w8: R29.2@628.44,1410.04 634.44,1404.03 634.44,1366.92 646.94,1366.92 674.74,1339.13 674.74,1305.17 695.39,1284.52 U6.39@718.5,1284.52 ; C34.1@641.8,1368.42 C34.1@645.44,1368.42
SLA: NT3.1 U6.11 | length 822.7
  Top Layer w8: U6.11@940.95,1081.76 942.06,1080.64 942.06,1062.01 947.96,1056.11 v1@1048.97,1056.11
  POWER w8: v1@1049.24,1058.94 1118.29,989.89 1118.29,502.52 1137.03,483.78 NT3.1@1218.64,483.78
  other v1: 1047.99,1060.47
SLB: NT5.1 U6.14 | length 222.4
  Top Layer w10: U6.14@992.09,1126.92 1033.57,1126.92 v1@1051.26,1109.22
  POWER w10: v1@1051.15,1110.4 1080.93,1080.62 v1@1194.67,1080.62
  other v1: 1193.58,1083.24 1049.5,1111.2
SLC: NT7.1 U6.21 | length 409
  Top Layer w8: U6.21@986.22,1264.83 987.34,1265.95 1002.6,1265.95 1029.09,1292.44 1029.09,1353.34 v1@1074.91,1399.16
  POWER w8: v1@1075.15,1398.37 1075.15,1481.18 1145.32,1551.35 v1@1192.29,1551.35
  other v1: 1075.47,1399.53 1193.44,1553.98
SPI_CLK: J3.15 R34.2 R50.1 U6.31 | length 3924.4
  Top Layer w8: v1@297.44,219.5 404.96,111.99 R50.1@583.28,111.99 ; U6.31@842.52,1349.48 842.52,1445.14 923.07,1525.69 R34.2@923.07,1560.85 ; v1@923.53,1604.74 923.53,1566.57 R34.2@929.97,1560.13
  POWER w8: v1@301.79,217.76 301.79,298.17 271.8,328.16 271.8,635.92 252.85,654.87 252.85,1124.04 213.83,1163.05 190.23,1186.68 190.23,1936 337.43,2083.2 641.34,2083.2 v1@645.87,2087.72
  Bottom Layer w8: v1@650.39,2083.17 901.58,2083.17 923.62,2061.12 v1(923.62,1604.74) ; J3.15@765.44,1812.21 765.44,1754.63 915.77,1604.3 v1@925.88,1604.3
  other v1: 299.36,219.23 648.6,2085.42
SPI_CS: J3.18 U6.32 | length 757.7
  Top Layer w8: U6.32@822.83,1349.48 822.83,1450.69 885.93,1513.78 v1@885.93,1674.18
  Bottom Layer w8: J3.18@865.44,2033.86 819.21,1987.63 819.21,1744.75 887.47,1676.49 v1@887.47,1674.47
  other v1: 886.61,1675.63
SPI_DRV_SDI: U6.30 U10.2 | length 980.9
  Top Layer w8: U10.2@271.14,1753.37 v1@341.01,1753.37 ; v1@490.54,1649.45 513.06,1626.94 v1(809.01,1626.94) ; U6.30@862.2,1349.48 862.2,1431.84 929.35,1498.99 v1@948.11,1498.99
  POWER w8: v1(339.9,1757.75) 381.5,1757.75 v1@488.48,1650.77
  Bottom Layer w8: v1(809.01,1626.94) 819.47,1626.94 v1@949.45,1496.95
  other v1: 946.67,1500.07 491.55,1648.65
SPI_DRV_SDO: R30.1 R31.1 U10.4 | length 1433.7
  Top Layer w8: R30.1@169.65,1713.37 U10.4@269.83,1713.37 ; v1@733.82,1694.08 815.17,1694.08 835.06,1713.98 994.47,1713.98 1026.64,1681.8 1026.64,1499.05 R31.1@986.19,1458.6
  POWER w8: v1@216.41,1711.94 216.41,1763.64 290.16,1837.39 689.85,1837.39 v1@720.6,1868.14
  Bottom Layer w8: v1@716.06,1867.47 716.06,1711.39 v1(732.97,1694.49)
  other v1: 215.69,1709.04 716.68,1867.24
SPI_MISO: J3.14 U10.6 | length 504.7
  Top Layer w8: U10.6@437.16,1693.69 492.57,1693.69 513.21,1714.33 513.21,1758.87 v1@517.67,1763.33
  Bottom Layer w8: v1@519.06,1758.32 513.65,1763.72 513.65,1858.58 523.88,1868.81 580.11,1868.81 672.91,1961.62 J3.14@672.91,2026.39
  other v1: 516.29,1762.47
SPI_MOSI: R56.2 U10.10 | length 112.1
  Top Layer w8: U10.10@445.76,1772.72 451.05,1772.72 513.79,1835.47 R56.2@513.79,1853.52
Temp: J4.3 U5.3 | length 1811.6
  Top Layer w10: v1@63.43,655.89 J4.3@63.43,717.29 ; v1@121.47,240.87 294.35,67.99 731.8,67.99 792.28,128.48 v1(1123.51,128.48)
  POWER w10: v1@63.34,657.03 118.92,601.45 v1(118.92,240.08)
  Bottom Layer w10: v1@1125.61,127.75 1189.68,127.75 1268.41,206.48 U5.3@1304.56,206.48
  other v1: 63.15,656.77
V_A: C4.1 R3.2 R6.2 R48.2 | length 1582.1
  Top Layer w8: v1@500.72,382.15 500.72,339.38 551.87,288.24 v1(551.87,204.96)
  POWER w8: v1@382.3,529.6 382.3,498.35 v1(496.83,383.81) ; v1@552.11,206.25 682.39,206.25 718.22,170.42 v1(1290.57,170.42)
  Bottom Layer w8: v1(381.99,529.39) R48.2@474.84,529.39 ; R48.2@473.79,518.29 R48.2@477.98,522.48 ; v1@1291.36,172.03 R3.2@1629.82,172.03
V_B: C7.1 R8.2 R10.2 R47.2 | length 1778.1
  Top Layer w8: v1@820.86,74.76 1337.14,74.76 v1@1385.25,122.87 ; v1(1385.39,123.01) v1@1385.25,122.87 ; R8.2@1630.29,122.87 v1@1385.25,122.87
  POWER w8: 311.69,508.63 316.98,513.92 v1@316.98,588.12 ; 315.06,511.46 301.34,497.75 301.34,348.18 508.09,141.43 650.47,141.43 651.99,139.91 671.74,139.91 673.26,141.43 750.75,141.43 v1@818.49,73.7
  Bottom Layer w8: R47.2@317.14,520.63 v1(317.14,586.41)
  other v1: 816.92,74.89
V_C: C10.1 R12.2 R17.2 R46.2 | length 1998.4
  POWER w8: v1@143.55,466.34 143.55,144.86 v1(239.32,49.09)
  Bottom Layer w8: v1(149.07,474.21) 190.64,515.77 R46.2@273.17,515.77 ; v1@239.28,49.79 1021.23,49.79 1044.56,73.13 R12.2@1629.78,73.13
V_Gate_driver: C13.2 J4.1 R19.1 R21.2 | length 218.9
  Top Layer w8: J4.1@266.52,743.9 282.75,760.13 R21.2@478.66,760.13
Vbus: C2.1 R1.2 R4.2 R49.2 | length 2366.2
  POWER w10: v1@438.74,658.07 382.04,658.07 278.29,761.81 278.29,1285.8 278.15,1285.94 278.15,1553.87 336.63,1612.35 492.57,1612.35 542.34,1662.12 542.34,1765.81 575.46,1798.93 720.33,1798.93 817.99,1896.59 817.99,2000.36 ; 817.95,2000.36 v1@817.95,2158.22
  Bottom Layer w10: v1@433.56,657.16 433.56,620.34 503.68,550.22 503.68,534.55 R49.2@518.34,519.9 ; v1@817.3,2153.35 R1.2@1011.44,2153.35
  other v1: 433.16,657.95 817.96,2153.78
VCP: C17.1 U6.7 | length 188.5
  Top Layer w8: U6.7@862.2,1081.76 862.2,1031.1 939.54,953.77 C17.1@968.05,953.77
Vencoder: C68.1 J7.1 R59.1 U8.6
